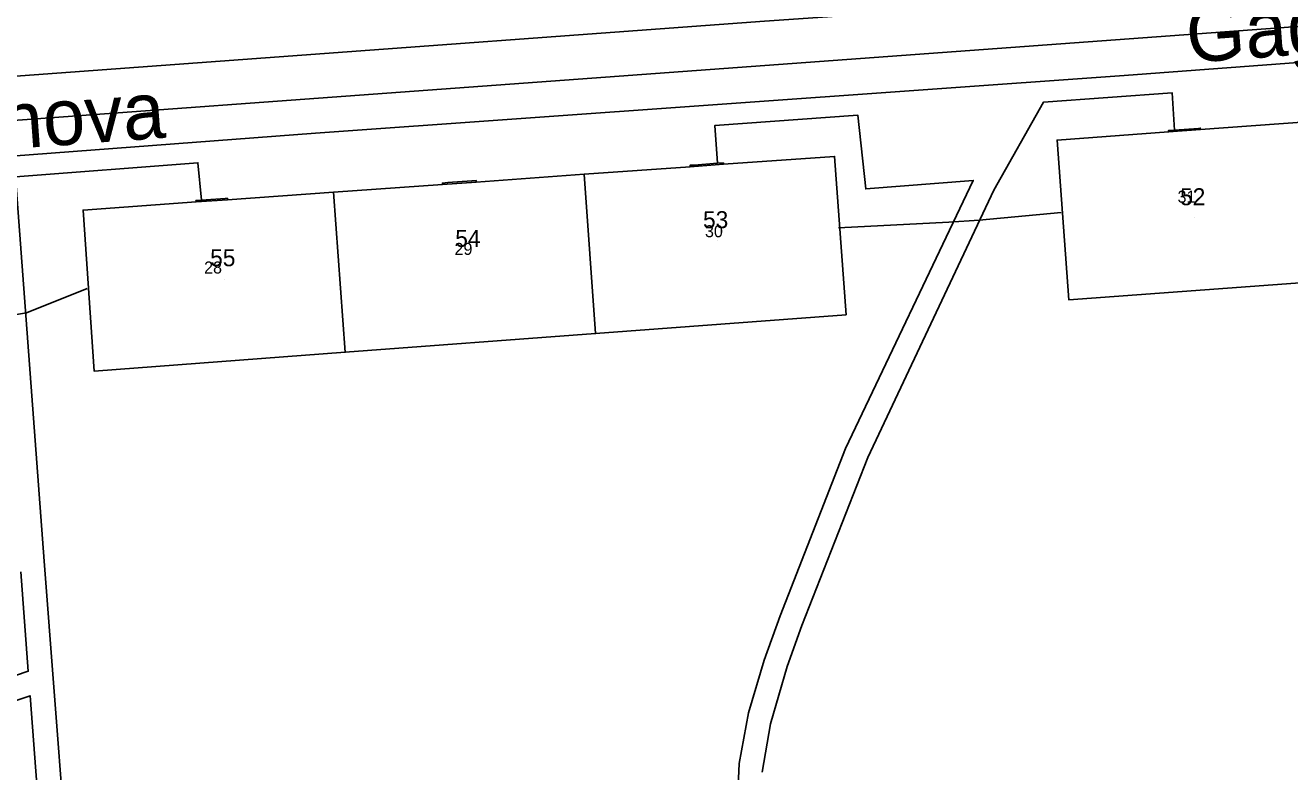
# Model space of a CAD drawing. Extents: x -873642 to -872917, y -1012962 to -1012567.
# Drawn here: x -873373.1 to -873283.8, y -1012748.5 to -1012695.8 of the extents above; entities that cross this region are included whole.
import ezdxf

# ---------------------------------------------------------------- set-up
doc = ezdxf.new("R2010")
doc.units = 0
for name, color, linetype in [('adresni_misto', 7, 'Continuous'), ('cisla_parcelni_kn', 7, 'Continuous'), ('cislo_domovni', 7, 'Continuous'), ('osy_ulic', 7, 'Continuous'), ('parcely_kn', 7, 'Continuous'), ('stavebni_objekty_bydleni', 7, 'Continuous'), ('TRASY - zamereno', 7, 'Continuous'), ('ulice', 7, 'Continuous')]:
    doc.layers.add(name, color=color, linetype=linetype)

msp = doc.modelspace()

# ---------------------------------------------------------------- linework, layer by layer
at = {"layer": 'adresni_misto'}
for p, q in [((-873290.5, -1012709.44), (-873290.5, -1012709.44)), ((-873324.19, -1012711.06), (-873324.19, -1012711.06)), ((-873341.69, -1012712.38), (-873341.69, -1012712.38)), ((-873359, -1012713.75), (-873359, -1012713.75))]:
    msp.add_line(p, q, dxfattribs=at)
at = {"layer": 'osy_ulic'}
msp.add_lwpolyline([(-873471.18, -1012707.47), (-873461.09, -1012708.93), (-873257.79, -1012694.05), (-873080.41, -1012681.66)], dxfattribs=at)
at = {"layer": 'parcely_kn'}
for points in [[(-873095.85, -1012678.72), (-873263.61, -1012691.39), (-873266.56, -1012691.78), (-873320.85, -1012695.55), (-873397.76, -1012701.2), (-873419.57, -1012702.63), (-873457.18, -1012705.12), (-873461.77, -1012705), (-873467.35, -1012700.29), (-873470.31, -1012685.53), (-873471.34, -1012679.34), (-873473.95, -1012664.84), (-873474.55, -1012659.21), (-873476.91, -1012642.49), (-873476.25, -1012638.16), (-873474.09, -1012635.88), (-873470.15, -1012634.51), (-873407.08, -1012629.93)], [(-873095.85, -1012678.72), (-873263.61, -1012691.39), (-873266.56, -1012691.78), (-873320.85, -1012695.55), (-873397.76, -1012701.2), (-873419.57, -1012702.63), (-873457.18, -1012705.12), (-873461.77, -1012705), (-873467.35, -1012700.29), (-873470.31, -1012685.53), (-873471.34, -1012679.34), (-873473.95, -1012664.84), (-873474.55, -1012659.21), (-873476.91, -1012642.49), (-873476.25, -1012638.16), (-873474.09, -1012635.88), (-873470.15, -1012634.51), (-873407.08, -1012629.93)], [(-873266.47, -1012697.2), (-873295.44, -1012699.37), (-873352.55, -1012703.45), (-873395.53, -1012706.69), (-873428.59, -1012709.13), (-873453.64, -1012710.91), (-873455.72, -1012711.3), (-873458.12, -1012712.14), (-873459.66, -1012713.44), (-873460.89, -1012715.04), (-873461.46, -1012716.61), (-873461.56, -1012718.11), (-873461.39, -1012719.27), (-873467.35, -1012700.29), (-873461.77, -1012705), (-873457.18, -1012705.12), (-873419.57, -1012702.63), (-873397.76, -1012701.2), (-873320.85, -1012695.55), (-873266.56, -1012691.78)], [(-873266.47, -1012697.2), (-873295.44, -1012699.37), (-873352.55, -1012703.45), (-873395.53, -1012706.69), (-873428.59, -1012709.13), (-873453.64, -1012710.91), (-873455.72, -1012711.3), (-873458.12, -1012712.14), (-873459.66, -1012713.44), (-873460.89, -1012715.04), (-873461.46, -1012716.61), (-873461.56, -1012718.11), (-873461.39, -1012719.27), (-873467.35, -1012700.29), (-873461.77, -1012705), (-873457.18, -1012705.12), (-873419.57, -1012702.63), (-873397.76, -1012701.2), (-873320.85, -1012695.55), (-873266.56, -1012691.78)], [(-873395.53, -1012706.69), (-873352.55, -1012703.45), (-873295.44, -1012699.37), (-873266.47, -1012697.2)], [(-873395.53, -1012706.69), (-873352.55, -1012703.45), (-873295.44, -1012699.37), (-873266.47, -1012697.2)], [(-873321.02, -1012748.59), (-873320.43, -1012745.18), (-873319.25, -1012741.13), (-873318.22, -1012738.22), (-873313.56, -1012726.35), (-873304.64, -1012707.48), (-873301.14, -1012701.26), (-873292.05, -1012700.61), (-873291.89, -1012703.23), (-873292.31, -1012703.26), (-873292.31, -1012703.36), (-873300.19, -1012703.94), (-873299.35, -1012715.23), (-873281.74, -1012713.93)], [(-873282.58, -1012702.64), (-873290.06, -1012703.19), (-873290.07, -1012703.09), (-873290.19, -1012703.11), (-873291.89, -1012703.23), (-873292.05, -1012700.61), (-873301.14, -1012701.26), (-873304.64, -1012707.48), (-873313.56, -1012726.35), (-873318.22, -1012738.22), (-873319.25, -1012741.13), (-873320.43, -1012745.18), (-873321.02, -1012748.59)], [(-873321.02, -1012748.59), (-873320.43, -1012745.18), (-873319.25, -1012741.13), (-873318.22, -1012738.22), (-873313.56, -1012726.35), (-873304.64, -1012707.48), (-873301.14, -1012701.26), (-873292.05, -1012700.61), (-873291.89, -1012703.23), (-873292.31, -1012703.26), (-873292.31, -1012703.36), (-873300.19, -1012703.94), (-873299.35, -1012715.23), (-873281.74, -1012713.93)], [(-873282.58, -1012702.64), (-873290.06, -1012703.19), (-873290.07, -1012703.09), (-873290.19, -1012703.11), (-873291.89, -1012703.23), (-873292.05, -1012700.61), (-873301.14, -1012701.26), (-873304.64, -1012707.48), (-873313.56, -1012726.35), (-873318.22, -1012738.22), (-873319.25, -1012741.13), (-873320.43, -1012745.18), (-873321.02, -1012748.59)], [(-873369.57, -1012761.6), (-873371.72, -1012733.69), (-873373.75, -1012706.54), (-873360.86, -1012705.54), (-873360.61, -1012708.18), (-873361, -1012708.21), (-873360.99, -1012708.31), (-873368.97, -1012708.88), (-873368.2, -1012720.25), (-873350.46, -1012718.92), (-873332.78, -1012717.6), (-873315.09, -1012716.27), (-873315.9, -1012705.09), (-873323.75, -1012705.65), (-873323.75, -1012705.55), (-873324.17, -1012705.58), (-873324.35, -1012702.9), (-873314.25, -1012702.18), (-873313.7, -1012707.39), (-873306.1, -1012706.79), (-873315.13, -1012725.73), (-873319.75, -1012737.54), (-873320.86, -1012740.66), (-873321.97, -1012744.4), (-873322.63, -1012747.98), (-873322.84, -1012752.76)], [(-873322.84, -1012752.76), (-873322.63, -1012747.98), (-873321.97, -1012744.4), (-873320.86, -1012740.66), (-873319.75, -1012737.54), (-873315.13, -1012725.73), (-873306.1, -1012706.79), (-873313.7, -1012707.39), (-873314.25, -1012702.18), (-873324.35, -1012702.9), (-873324.17, -1012705.58), (-873325.82, -1012705.7), (-873326.1, -1012705.72), (-873326.09, -1012705.82), (-873333.59, -1012706.35), (-873341.2, -1012706.9), (-873341.2, -1012706.8), (-873341.51, -1012706.82), (-873343.21, -1012706.94), (-873343.59, -1012706.97), (-873343.58, -1012707.07), (-873351.28, -1012707.62), (-873358.78, -1012708.15), (-873358.78, -1012708.05), (-873358.95, -1012708.06), (-873360.61, -1012708.18), (-873360.86, -1012705.54), (-873373.75, -1012706.54), (-873371.72, -1012733.69), (-873369.57, -1012761.6)], [(-873369.57, -1012761.6), (-873371.72, -1012733.69), (-873373.75, -1012706.54), (-873360.86, -1012705.54), (-873360.61, -1012708.18), (-873361, -1012708.21), (-873360.99, -1012708.31), (-873368.97, -1012708.88), (-873368.2, -1012720.25), (-873350.46, -1012718.92), (-873332.78, -1012717.6), (-873315.09, -1012716.27), (-873315.9, -1012705.09), (-873323.75, -1012705.65), (-873323.75, -1012705.55), (-873324.17, -1012705.58), (-873324.35, -1012702.9), (-873314.25, -1012702.18), (-873313.7, -1012707.39), (-873306.1, -1012706.79), (-873315.13, -1012725.73), (-873319.75, -1012737.54), (-873320.86, -1012740.66), (-873321.97, -1012744.4), (-873322.63, -1012747.98), (-873322.84, -1012752.76)], [(-873322.84, -1012752.76), (-873322.63, -1012747.98), (-873321.97, -1012744.4), (-873320.86, -1012740.66), (-873319.75, -1012737.54), (-873315.13, -1012725.73), (-873306.1, -1012706.79), (-873313.7, -1012707.39), (-873314.25, -1012702.18), (-873324.35, -1012702.9), (-873324.17, -1012705.58), (-873325.82, -1012705.7), (-873326.1, -1012705.72), (-873326.09, -1012705.82), (-873333.59, -1012706.35), (-873341.2, -1012706.9), (-873341.2, -1012706.8), (-873341.51, -1012706.82), (-873343.21, -1012706.94), (-873343.59, -1012706.97), (-873343.58, -1012707.07), (-873351.28, -1012707.62), (-873358.78, -1012708.15), (-873358.78, -1012708.05), (-873358.95, -1012708.06), (-873360.61, -1012708.18), (-873360.86, -1012705.54), (-873373.75, -1012706.54), (-873371.72, -1012733.69), (-873369.57, -1012761.6)], [(-873373.38, -1012734.43), (-873372.85, -1012741.46), (-873391.67, -1012747.88)], [(-873391.67, -1012747.88), (-873372.85, -1012741.46), (-873373.38, -1012734.43)], [(-873373.38, -1012734.43), (-873372.85, -1012741.46), (-873391.67, -1012747.88)], [(-873391.67, -1012747.88), (-873372.85, -1012741.46), (-873373.38, -1012734.43)], [(-873391.16, -1012749.27), (-873372.72, -1012743.18), (-873371.35, -1012761.35)], [(-873371.35, -1012761.35), (-873372.72, -1012743.18), (-873391.16, -1012749.27)], [(-873391.16, -1012749.27), (-873372.72, -1012743.18), (-873371.35, -1012761.35)], [(-873371.35, -1012761.35), (-873372.72, -1012743.18), (-873391.16, -1012749.27)]]:
    msp.add_lwpolyline(points, dxfattribs=at)
for points in [[(-873282.58, -1012702.64), (-873281.74, -1012713.93), (-873299.35, -1012715.23), (-873300.19, -1012703.94), (-873292.31, -1012703.36), (-873292.31, -1012703.26), (-873291.89, -1012703.23), (-873290.19, -1012703.11), (-873290.07, -1012703.09), (-873290.06, -1012703.19)], [(-873282.58, -1012702.64), (-873281.74, -1012713.93), (-873299.35, -1012715.23), (-873300.19, -1012703.94), (-873292.31, -1012703.36), (-873292.31, -1012703.26), (-873291.89, -1012703.23), (-873290.19, -1012703.11), (-873290.07, -1012703.09), (-873290.06, -1012703.19)], [(-873315.9, -1012705.09), (-873315.09, -1012716.27), (-873332.78, -1012717.6), (-873333.59, -1012706.35), (-873326.09, -1012705.82), (-873326.1, -1012705.72), (-873325.82, -1012705.7), (-873324.17, -1012705.58), (-873323.75, -1012705.55), (-873323.75, -1012705.65)], [(-873315.9, -1012705.09), (-873315.09, -1012716.27), (-873332.78, -1012717.6), (-873333.59, -1012706.35), (-873326.09, -1012705.82), (-873326.1, -1012705.72), (-873325.82, -1012705.7), (-873324.17, -1012705.58), (-873323.75, -1012705.55), (-873323.75, -1012705.65)], [(-873333.59, -1012706.35), (-873332.78, -1012717.6), (-873350.46, -1012718.92), (-873351.28, -1012707.62), (-873343.58, -1012707.07), (-873343.59, -1012706.97), (-873343.21, -1012706.94), (-873341.51, -1012706.82), (-873341.2, -1012706.8), (-873341.2, -1012706.9)], [(-873333.59, -1012706.35), (-873332.78, -1012717.6), (-873350.46, -1012718.92), (-873351.28, -1012707.62), (-873343.58, -1012707.07), (-873343.59, -1012706.97), (-873343.21, -1012706.94), (-873341.51, -1012706.82), (-873341.2, -1012706.8), (-873341.2, -1012706.9)], [(-873351.28, -1012707.62), (-873350.46, -1012718.92), (-873368.2, -1012720.25), (-873368.97, -1012708.88), (-873360.99, -1012708.31), (-873361, -1012708.21), (-873360.61, -1012708.18), (-873358.95, -1012708.06), (-873358.78, -1012708.05), (-873358.78, -1012708.15)], [(-873351.28, -1012707.62), (-873350.46, -1012718.92), (-873368.2, -1012720.25), (-873368.97, -1012708.88), (-873360.99, -1012708.31), (-873361, -1012708.21), (-873360.61, -1012708.18), (-873358.95, -1012708.06), (-873358.78, -1012708.05), (-873358.78, -1012708.15)]]:
    msp.add_lwpolyline(points, close=True, dxfattribs=at)
at = {"layer": 'stavebni_objekty_bydleni'}
for points in [[(-873274.59, -1012702.04), (-873272.7, -1012701.9), (-873264.91, -1012701.33), (-873257.33, -1012700.77), (-873255.18, -1012700.61), (-873247.25, -1012700.02), (-873246.41, -1012711.33), (-873264.07, -1012712.63), (-873281.74, -1012713.93), (-873299.35, -1012715.23), (-873300.19, -1012703.94), (-873292.31, -1012703.36), (-873290.06, -1012703.19), (-873282.58, -1012702.64), (-873275.04, -1012702.07)], [(-873315.9, -1012705.09), (-873315.09, -1012716.27), (-873332.78, -1012717.6), (-873350.46, -1012718.92), (-873368.2, -1012720.25), (-873368.97, -1012708.88), (-873360.99, -1012708.31), (-873358.78, -1012708.15), (-873351.28, -1012707.62), (-873343.58, -1012707.07), (-873341.2, -1012706.9), (-873333.59, -1012706.35), (-873326.09, -1012705.82), (-873323.75, -1012705.65)]]:
    msp.add_lwpolyline(points, close=True, dxfattribs=at)
at = {"layer": 'TRASY - zamereno'}
for p, q in [((-873299.89, -1012709.06), (-873305.68, -1012709.6)), ((-873307.82, -1012709.74), (-873315.62, -1012710.14)), ((-873305.68, -1012709.6), (-873307.82, -1012709.74)), ((-873368.69, -1012714.43), (-873372.98, -1012716.15)), ((-873372.98, -1012716.15), (-873374.94, -1012716.48))]:
    msp.add_line(p, q, dxfattribs=at)

# ---------------------------------------------------------------- texts
at = {"layer": 'cisla_parcelni_kn'}
for s, p in [('31', (-873291.677, -1012708.363)), ('31', (-873291.677, -1012708.363)), ('30', (-873325.052, -1012710.8)), ('30', (-873325.052, -1012710.8)), ('29', (-873342.74, -1012712.05)), ('29', (-873342.74, -1012712.05)), ('28', (-873360.427, -1012713.363)), ('28', (-873360.427, -1012713.363))]:
    msp.add_text(s, height=0.85, dxfattribs=at).set_placement(p)
at = {"layer": 'cislo_domovni'}
for s, p in [('52', (-873291.5, -1012708.54)), ('53', (-873325.19, -1012710.16)), ('54', (-873342.69, -1012711.48)), ('55', (-873360, -1012712.85))]:
    msp.add_text(s, height=1.2, dxfattribs=at).set_placement(p)
at = {"layer": 'ulice'}
for p in [(-873290.927, -1012698.481), (-873390.66, -1012705.78)]:
    msp.add_text('Gagarinova', height=4, rotation=4.18615, dxfattribs=at).set_placement(p)

doc.saveas('drawing.dxf')
